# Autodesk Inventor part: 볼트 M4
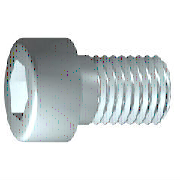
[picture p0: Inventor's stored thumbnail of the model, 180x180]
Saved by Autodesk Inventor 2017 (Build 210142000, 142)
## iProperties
IsCustomPart: 0
Created: 2018-09
Part Number: 볼트 M4
Material: 스테인리스강
Description: 6각머리 태핑 나사
Document SubType Name: Modeling
Standard: KS B 1003
Standards Organization: KS
Language: ko-KR
Size Designation: M 4 x 10
Categories: <MemberInstance><Categories><Category DisplayName="조임쇠" InternalName="e4da775c-781d-43d5-af7c-5136215cf5a6" Mnemonic="FSTN"><Category DisplayName="볼트" InternalN
Density: 8.08 g/cm^3
Appearance: 반광택
Mass: 2.09412 g
Surface Area: 3.0572 cm^2
Volume: 0.259174 cm^3
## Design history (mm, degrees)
sketch "스케치1"
  geometry: L1 (-1, 0)-(10, 0); L2 (10, 0)-(10, 2); L3 (10, 2)-(1.75, 2); L4 (1.75, 2)-(1.32, 2); L5 (1.32, 2)-(0, 2); L6 (0, 2)-(0, 3.5); L7 (0, 3.5)-(-4, 3.5); L8 (-4, 3.5)-(-4, 1.732); L9 (-4, 1.732)-(-2, 1.732); L10 (-2, 1.732)-(-1, 0); L11 (-6.8, 0)-(12.8, 0) reference; L12 (0, -0.7)-(0, 4.2) reference; L13 (1.75, 2)-(0, 2)
  constraints: 22 end point, 6 parallel, 2 collinear, 2 perpendicular, 1 horizontal, 1 point on line
  dimensions: "d1" = 8.25 distance from line of L3.end L2 (= GEL); "d2" = 0.42952 distance of L4.end L3.end (computed from GAL); "d3" = 4 distance between parallel lines of L8 L6 (= KOH); "d4" = 2 distance of L8.end L9.end (= INTI); "d5" = 60 deg angle of L10 L1; "d6" = 4 diameter of L3 L1 (= GD); "d7" = 4 diameter of L5 L1 (= BDM); "d8" = 3.4641 diameter of L9 L1 (= 1.1547 x SW); "d9" = 7 diameter of L7 L1 (= KOD); "d26" = 10 distance between parallel lines of L12 L2 (= NLG)
revolve "본체" sketch "스케치1" stored, may be unused: angle "d10" = 90 deg
sketch "스케치2"
  geometry: L1 (0, -4.9)-(0, 4.9) reference; L2 (-4.9, 0)-(4.9, 0) reference; L3 (1.732, 0)-(0.866, -1.5); L4 (0.866, -1.5)-(-0.866, -1.5); L5 (-0.866, -1.5)-(-1.732, 0); L6 (-1.732, 0)-(-0.866, 1.5); L7 (-0.866, 1.5)-(0.866, 1.5); L8 (0.866, 1.5)-(1.732, 0); 2 further points
  constraints: 12 end point, 1 coincident, 1 horizontal alignment, 1 point on line, 12 other
extrude "슬롯" join sketch "스케치2" stored distance "d11" = 10; taper "d12" = 0 deg
workplane "Work Plane1"
fillet "Fillet2" dims "d30" = 0.1 (= R)
body "Solid1"
fillet "모깎기1" dims "d17" = 0.4 (= RR)
feature "스레드" dims "d13" = 8.25 (= GEL), "d14" = 0
chamfer "모따기1" distance "d15" = 0.42941 (= -0.5 x SPD + 0.5 x GD); stored, may be unused: second distance "d16" = 0.42941 (= GUL), angle "d27" = 45 deg
other parameters: "GD" = 4 (= NND) [user parameter; used in 2 equation terms], "NLG" = 10 [user parameter; used in 1 equation term], "GEL" = 8.25 [user parameter; used in 2 equation terms], "KOD" = 7 [user parameter; used in 1 equation term], "KOH" = 4 [user parameter; used in 1 equation term], "INTI" = 2 [user parameter; used in 1 equation term], "GAL" = 0.42941 (= 0.61345 x PTC) [user parameter; used in 1 equation term], "GUL" = 0.42941 (= 0.61345 x PTC) [user parameter; used in 1 equation term], "BDM" = 4 (= NND) [user parameter; used in 1 equation term], "SW" = 3 [user parameter; used in 2 equation terms], "RR" = 0.4 [user parameter; used in 1 equation term], "SPD" = 3.14117 (= NND - 1.2269 x PTC) [user parameter; used in 1 equation term], "d19" = 0, "d28" = 0, "d29" = 0, "R" = 0.1 [user parameter; used in 1 equation term], "PHH" = 0.2 [user parameter], "GD1" = 3.14117 (= THREADDIA - 1.2269 x PTC) [user parameter], "THREADDIA" = 4 [user parameter; used in 1 equation term], "FAWI" = 45 deg [user parameter], "TPU" = 14.28571 (computed from PTC) [user parameter], "PTC" = 0.7 [user parameter; used in 5 equation terms], "NND" = 4 [user parameter; used in 3 equation terms], "TOA" = 30 deg [user parameter], "E0" = 3.465 (= 1.155 x SW) [user parameter]
